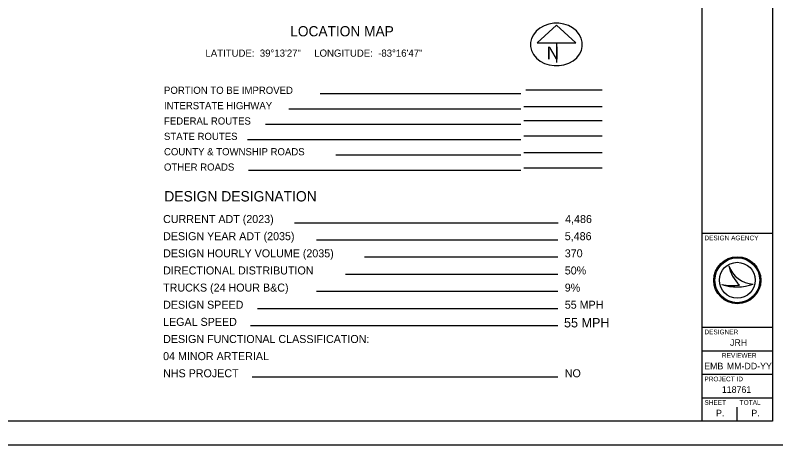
# Model space of a CAD drawing. Extents: x -139 to 835, y 0 to 440.
# Drawn here: x 348 to 671.4, y 0 to 182.8 of the extents above; entities that cross this region are included whole.
import ezdxf

# ---------------------------------------------------------------- set-up
doc = ezdxf.new("R2010")
doc.units = 0
for name, color, linetype in [('Default', 7, 'Continuous'), ('SH_Border', 7, 'Continuous'), ('SH_Cut_Line', 7, 'Continuous'), ('SH_Data', 7, 'Continuous'), ('SH_Text', 7, 'Continuous')]:
    doc.layers.add(name, color=color, linetype=linetype)

msp = doc.modelspace()

# ---------------------------------------------------------------- linework, layer by layer
at = {"layer": 'SH_Border'}
for p, q in [((640, 10), (640, 430)), ((640, 90), (670, 90)), ((640, 50), (670, 50)), ((640, 40), (670, 40)), ((640, 30), (670, 30)), ((640, 20), (670, 20))]:
    msp.add_line(p, q, dxfattribs=at)
msp.add_lwpolyline([(30, 430), (670, 430), (670, 10), (30, 10)], close=True, dxfattribs=at)
at = {"layer": 'SH_Cut_Line'}
msp.add_lwpolyline([(0, 0), (680, 0), (680, 440), (0, 440)], close=True, dxfattribs=at)
at = {"layer": 'SH_Data'}
for p, q in [((578.1, 178.46), (569.93, 171.03)), ((586.28, 171.03), (578.1, 178.46)), ((569.93, 171.03), (586.28, 171.03)), ((578.1, 171.03), (578.1, 162.61)), ((578.1, 170.32), (578.1, 170.32)), ((578.1, 170.32), (578.1, 170.32)), ((562.91, 149.31), (477.68, 149.31)), ((565.11, 151.02), (597.47, 151.02)), ((562.91, 142.77), (464.27, 142.77)), ((597.47, 143.73), (564.24, 143.73)), ((562.91, 136.24), (454.43, 136.24)), ((597.47, 137.82), (564.24, 137.82)), ((562.91, 129.71), (446.71, 129.71)), ((597.47, 131.28), (564.24, 131.28)), ((562.91, 123.17), (484.36, 123.17)), ((597.47, 124.17), (564.24, 124.17)), ((562.91, 116.64), (447.2, 116.64)), ((597.47, 117.63), (564.24, 117.63)), ((578.83, 94.34), (466.68, 94.34)), ((578.66, 87.05), (476.09, 87.05)), ((578.66, 79.76), (496.45, 79.76)), ((651.35, 76.19), (651.35, 76.19)), ((578.66, 72.47), (488.47, 72.47)), ((648.34, 68.19), (648.34, 68.19)), ((655, 70), (655, 70)), ((661.75, 68.37), (661.75, 68.37)), ((578.66, 65.18), (476.12, 65.18)), ((578.66, 57.89), (451.06, 57.89)), ((578.66, 50.6), (447.98, 50.6)), ((578.66, 28.73), (448.71, 28.73)), ((647.5, 13.5), (647.5, 13.5)), ((655, 10), (655, 16))]:
    msp.add_line(p, q, dxfattribs=at)
for radius in [10, 9.54, 9.54, 7.64]:
    msp.add_circle((655, 70), radius, dxfattribs=at)
for centre, radius, start, end in [((662.32, 79.95), 11.6, 198.9257, 198.9319), ((666.93, 79.4), 15.91, 191.6379, 191.6421), ((662.32, 79.95), 11.6, 198.9319, 267.1657), ((666.93, 79.4), 15.91, 191.6421, 226.0947), ((654.79, 87.4), 20.26, 251.4576, 290.0832), ((652.96, 93.09), 25.32, 259.4964, 259.4995), ((654.79, 87.4), 20.26, 251.4527, 251.4576), ((652.96, 93.09), 25.32, 259.4995, 276.6672)]:
    msp.add_arc(centre, radius, start, end, dxfattribs=at)
msp.add_ellipse((578.1, 170.32), major_axis=(-11.03, 0), ratio=0.819388, start_param=5.406678, end_param=11.689575, dxfattribs=at)

# ---------------------------------------------------------------- texts
at = {"layer": 'Default'}
msp.add_text('55 MPH', height=4, dxfattribs=at).set_placement((581.32, 49.94))
at = {"layer": 'SH_Data'}
for s, height, p in [('N', 5.45, (573.97, 163.98)), ('DESIGN DESIGNATION', 4.4037, (411.39, 103.52)), ('DESIGN AGENCY', 2, (641, 87)), ('DESIGNER', 2, (641, 47)), ('JRH', 2.8, (651.91, 42.1)), ('REVIEWER', 2, (648.44, 37)), ('EMB', 2.8, (640.93, 32.1)), ('MM-DD-YY', 2.8, (650.55, 32.1)), ('PROJECT ID', 2, (641, 27)), ('118761', 2.8, (648.42, 22.1)), ('SHEET', 2, (641, 17)), ('TOTAL', 2, (656, 17)), ('P.', 2.8, (645.97, 12.1)), ('P.', 2.8, (660.97, 12.1))]:
    msp.add_text(s, height=height, dxfattribs=at).set_placement(p)
at = {"layer": 'SH_Text'}
for s, height, p in [('LOCATION MAP', 4.3563, (464.92, 173.77)), ('LATITUDE:  39°13\'27"     LONGITUDE:  -83°16\'47"', 3.0494, (428.88, 165.11)), ('PORTION TO BE IMPROVED', 3.0494, (411.24, 149.31)), ('INTERSTATE HIGHWAY', 3.0494, (411.24, 142.77)), ('FEDERAL ROUTES', 3.0494, (411.24, 136.24)), ('STATE ROUTES', 3.0494, (411.24, 129.71)), ('COUNTY & TOWNSHIP ROADS', 3.0494, (411.24, 123.17)), ('OTHER ROADS', 3.0494, (411.24, 116.64)), ('CURRENT ADT (2023)', 3.4017, (410.87, 94.34)), ('4,486', 3.402, (581.8, 94.34)), ('DESIGN YEAR ADT (2035)', 3.4017, (410.87, 87.05)), ('5,486', 3.402, (581.64, 87.05)), ('DESIGN HOURLY VOLUME (2035)', 3.4017, (410.87, 79.76)), ('370', 3.402, (581.64, 79.76)), ('DIRECTIONAL DISTRIBUTION', 3.4017, (410.87, 72.47)), ('50%', 3.402, (581.64, 72.47)), ('TRUCKS (24 HOUR B&C)', 3.4017, (410.87, 65.18)), ('9%', 3.402, (581.64, 65.18)), ('DESIGN SPEED', 3.4017, (410.87, 57.89)), ('55 MPH', 3.402, (581.64, 57.89)), ('LEGAL SPEED', 3.4017, (410.87, 50.6)), ('DESIGN FUNCTIONAL CLASSIFICATION:', 3.4017, (410.87, 43.31)), ('04 MINOR ARTERIAL', 3.4017, (410.87, 36.02)), ('NHS PROJECT', 3.4017, (410.87, 28.73)), ('NO', 3.402, (581.64, 28.73))]:
    msp.add_text(s, height=height, dxfattribs=at).set_placement(p)

doc.saveas('drawing.dxf')
